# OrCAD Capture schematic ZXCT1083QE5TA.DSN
size Custom; title: ZXCT1083Q - PRECISION HIGH VOLTAGE HIGH-SIDE CURRENT MONITORS; rev: 1.0; note: DS37015  Rev. 1 - 2
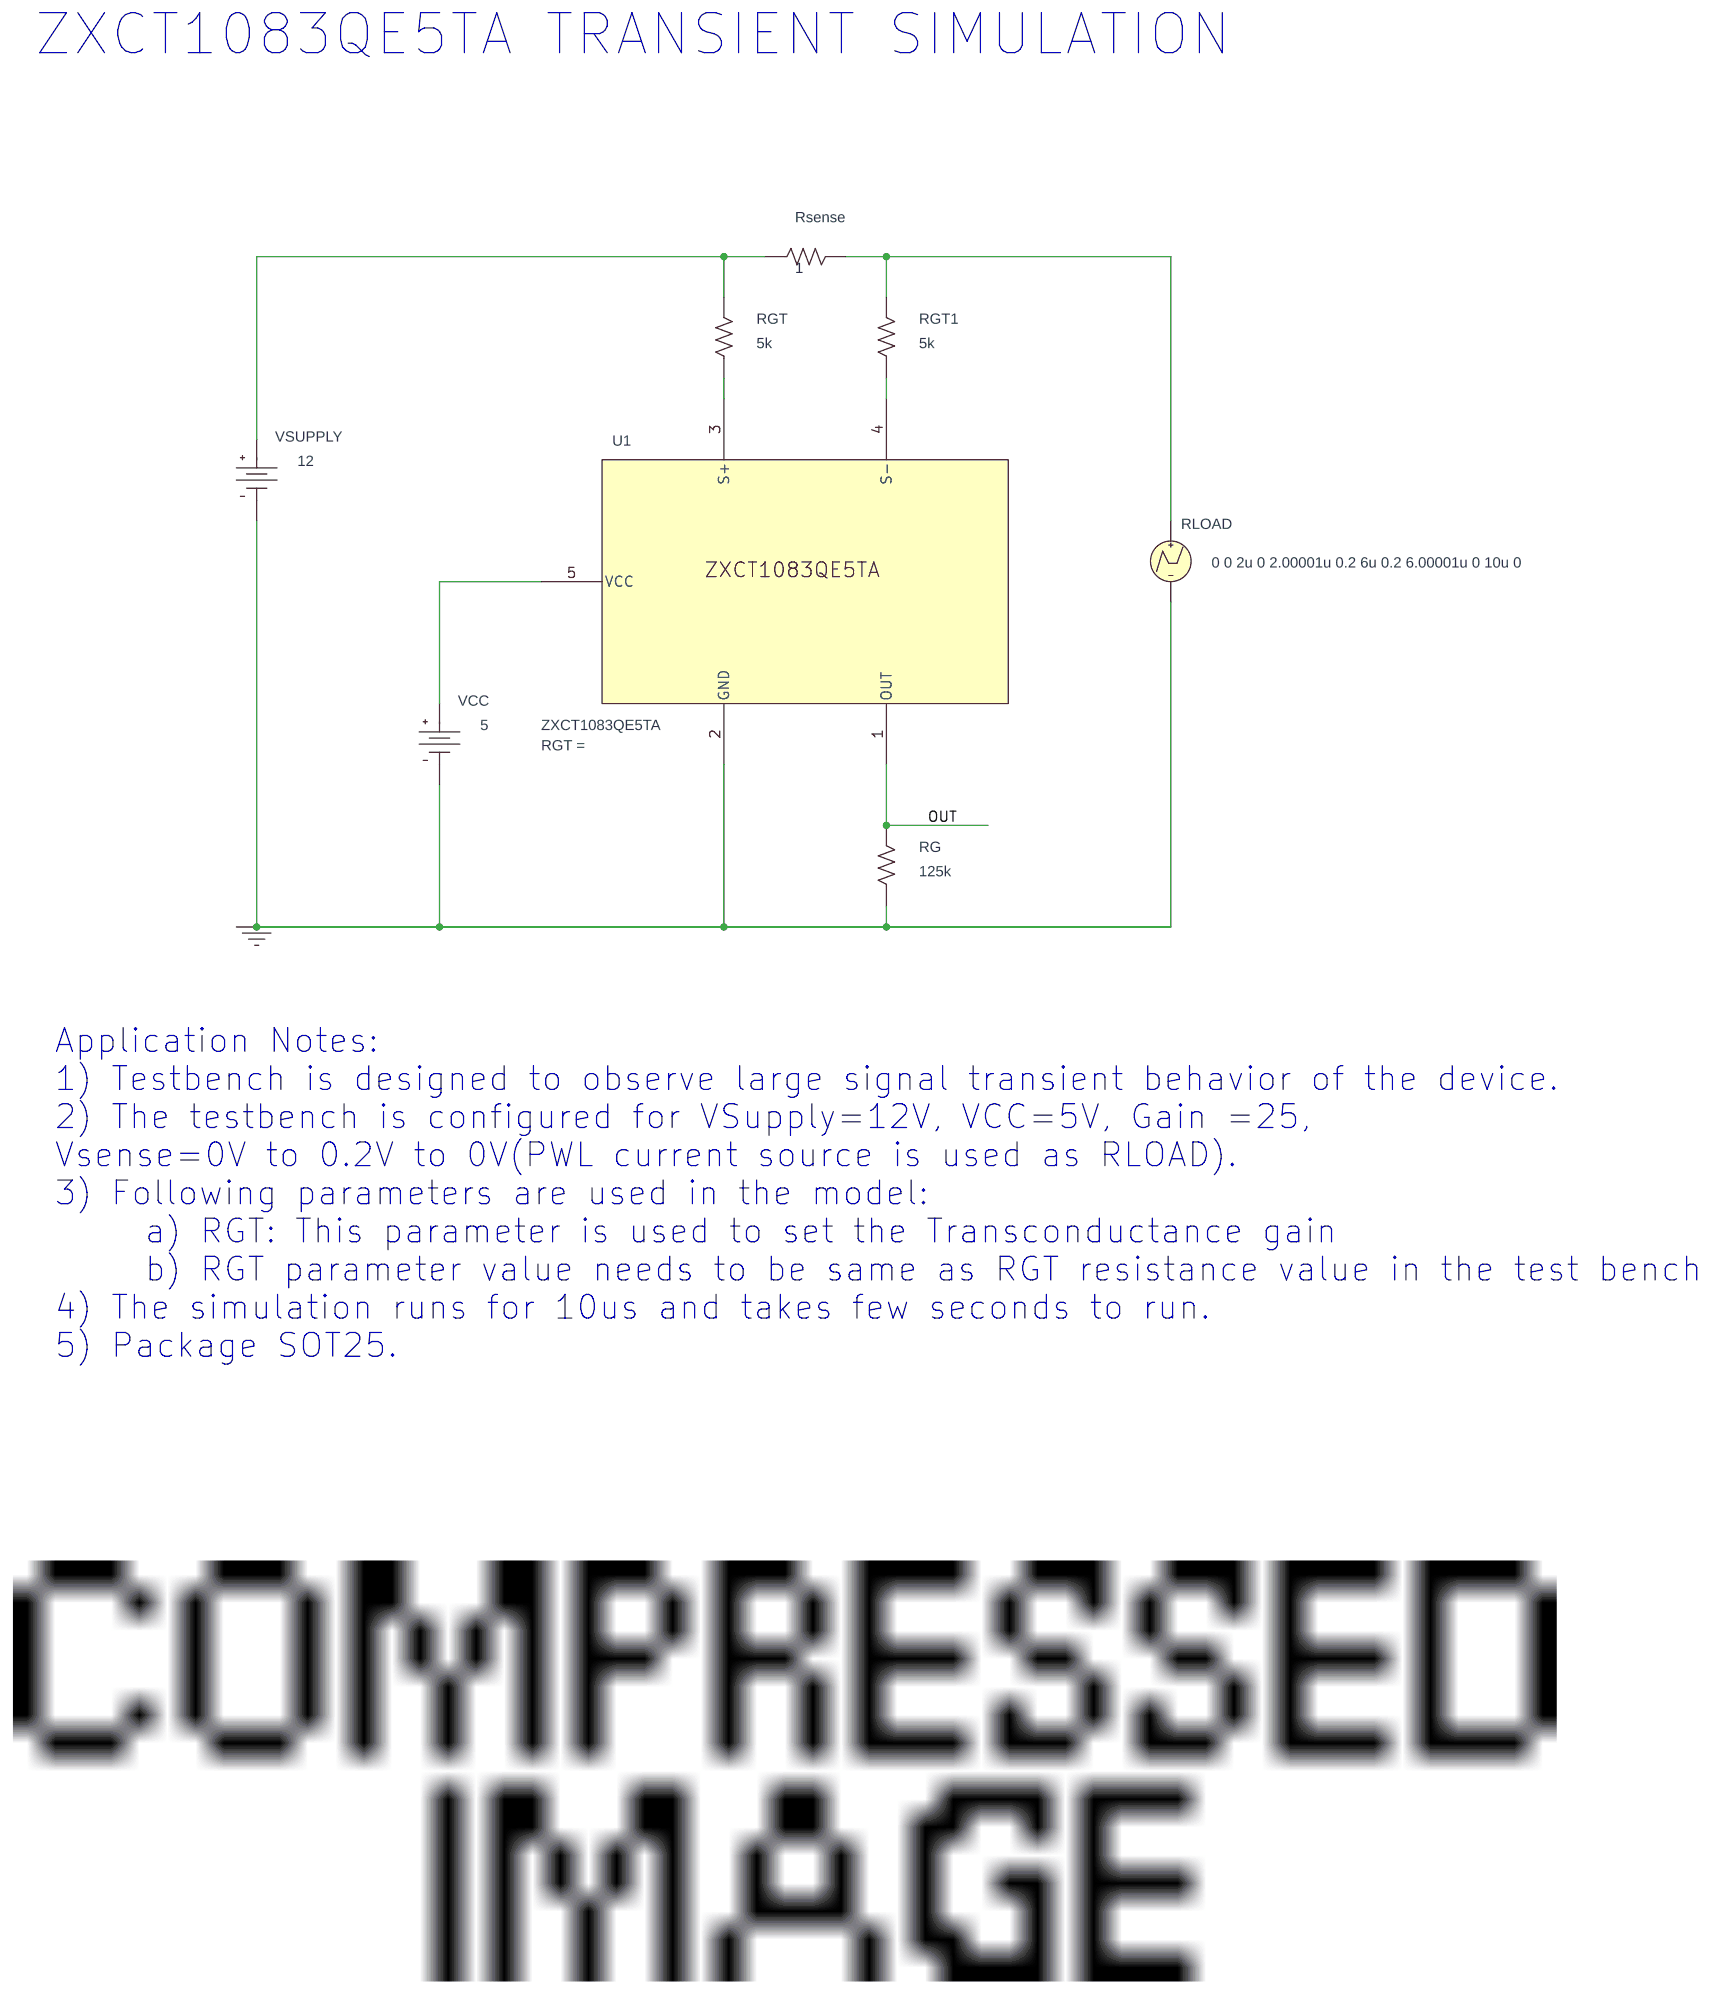
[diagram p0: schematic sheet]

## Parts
RG  125k  [AX/RC05]
RGT  5k  [AX/RC05]
RGT1  5k  [AX/RC05]
RLOAD  IPWL_GENERIC
Rsense  1  [AX/RC05]
U1  ZXCT1083QE5TA
VCC  VDC
VSUPPLY  VDC

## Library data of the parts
RG RGT RGT1 Rsense = R
RLOAD = IPWL_GENERIC: AppProp: No_reps$POINTS_TYPE_PWL$0$0; FIRST_NPAIRS: 0 0 2u 0 2.00001u 0.2 6u 0.2 6.00001u 0 10u 0; PSpiceTemplate: I^@REFDES %+ %- ?DC|DC @DC| ?AC|AC @AC| PWL ?TSF|TIME_SCALE_FACTOR=@TSF| ?VSF|VALUE_SCALE_FACTOR=@VSF| ?REPEAT_VALUE| \n+ REPEAT FOR @REPEAT_VALUE| \n+ @FIRST_NPAIRS ?SECOND_NPAIRS|\n+ @SECOND_NPAIRS ?THIRD_NPAIRS/\n+ @THIRD_NPAIRS/| ?REPEAT_VALUE| \n+ ENDREPEAT|
U1 = ZXCT1083QE5TA_2
VCC = VDC: DC: 5
VSUPPLY = VDC: DC: 12

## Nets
0: RG.1 RLOAD.2(-) U1.2(GND) VCC.1(-) VSUPPLY.1(-)
OUT: RG.2 U1.1(OUT)
N79135: U1.5(VCC) VCC.0(+)
N79159: RGT.2 Rsense.1 VSUPPLY.0(+)
N79193: RGT1.2 RLOAD.1(+) Rsense.2
N79355: RGT.1 U1.3(S+)
N79381: RGT1.1 U1.4(S-)

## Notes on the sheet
- ZXCT1083QE5TA TRANSIENT SIMULATION
- Application Notes:
  1) Testbench is designed to observe large signal transient behavior of the device.
  2) The testbench is configured for VSupply=12V, VCC=5V, Gain =25,
  Vsense=0V to 0.2V to 0V(PWL current source is used as RLOAD).
  3) Following parameters are used in the model:
       a) RGT: This parameter is used to set the Transconductance gain
       b) RGT parameter value needs to be same as RGT resistance value in the test bench
  4) The simulation runs for 10us and takes few seconds to run.
  5) Package SOT25.
